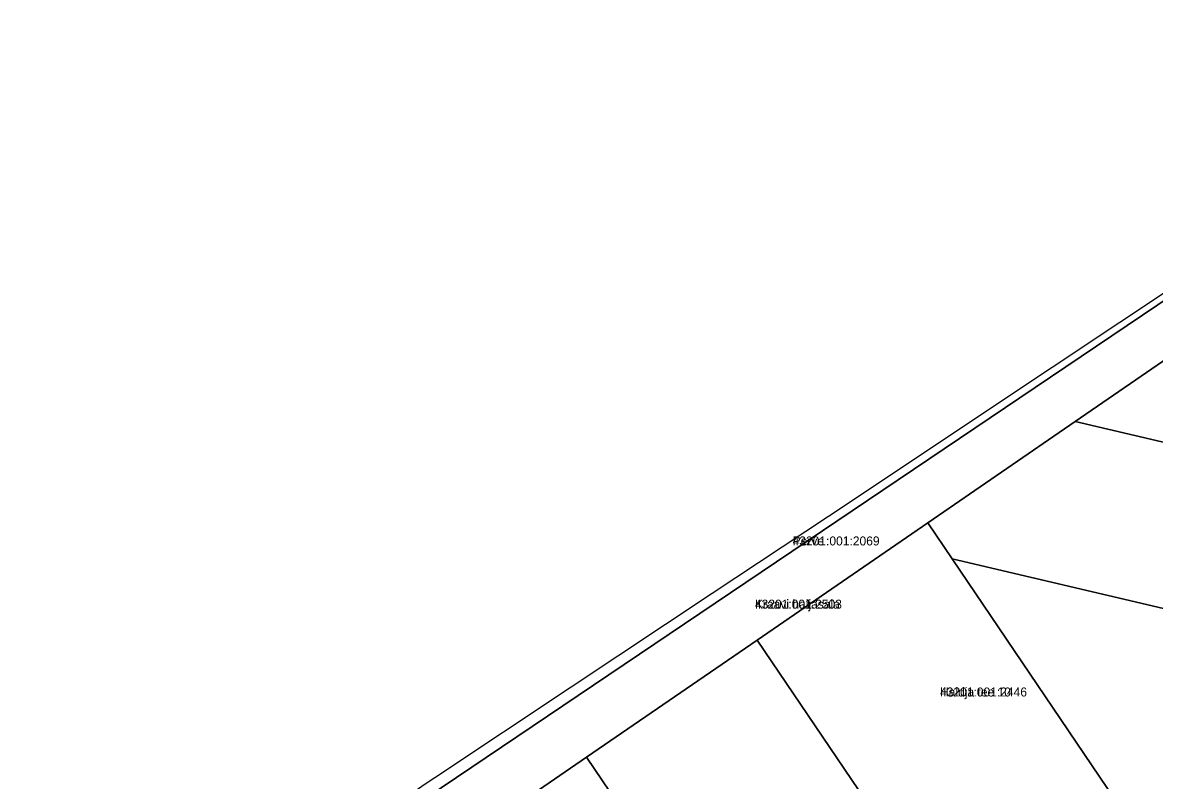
# Model space of a CAD drawing. Extents: x 661852 to 683758, y 6469495 to 6482657.
# Drawn here: x 663149.3 to 663337.9, y 6470350.3 to 6470476.5 of the extents above; entities that cross this region are included whole.
import ezdxf

# ---------------------------------------------------------------- set-up
doc = ezdxf.new("R2010")
doc.units = 0
for name, color, linetype in [('L_AADRESS', 7, 'Continuous'), ('PIIR', 7, 'Continuous'), ('TUNNUS', 7, 'Continuous')]:
    doc.layers.add(name, color=color, linetype=linetype)

msp = doc.modelspace()

# ---------------------------------------------------------------- linework, layer by layer
at = {"layer": 'PIIR'}
for points in [[(663386.73, 6470461.98), (663152.91, 6470304.5), (663149.63, 6470302.29), (663149.29, 6470302.91), (663152.5, 6470305.15), (663176.5, 6470321.88), (663197.37, 6470336.43), (663216.36, 6470349.67), (663217.96, 6470350.73), (663240.69, 6470365.84), (663264.21, 6470381.45), (663287.53, 6470396.88), (663309.62, 6470411.62), (663332.17, 6470426.61), (663387.19, 6470463.21), (663407.23, 6470476.53), (663407.44, 6470475.89), (663388.39, 6470463.06)], [(663158.41, 6470295.77), (663152.91, 6470304.5), (663386.73, 6470461.98), (663384.15, 6470450.91), (663324.73, 6470410.08), (663300.15, 6470393.19), (663271.71, 6470373.65), (663243.28, 6470354.11), (663214.84, 6470334.57), (663186.41, 6470315.03)], [(663376.34, 6470397.96), (663324.73, 6470410.08), (663384.15, 6470450.91), (663382.48, 6470443.81), (663386.86, 6470442.78)], [(663304.22, 6470387.16), (663300.15, 6470393.19), (663324.73, 6470410.08), (663376.34, 6470397.96), (663370.17, 6470371.68)], [(663297.09, 6470336.11), (663271.71, 6470373.65), (663300.15, 6470393.19), (663304.22, 6470387.16), (663332.64, 6470345.13), (663327.57, 6470345.04), (663316.44, 6470343.1), (663306.8, 6470340.26)], [(663332.64, 6470345.13), (663304.22, 6470387.16), (663370.17, 6470371.68), (663364.16, 6470346.08), (663359.35, 6470343.1), (663344.92, 6470345.34)], [(663267.97, 6470317.59), (663243.28, 6470354.11), (663271.71, 6470373.65), (663297.09, 6470336.11), (663285.82, 6470329.67)], [(663239.39, 6470298.27), (663214.84, 6470334.57), (663243.28, 6470354.11), (663267.97, 6470317.59)]]:
    msp.add_lwpolyline(points, close=True, dxfattribs=at)

# ---------------------------------------------------------------- texts
at = {"layer": 'L_AADRESS'}
for s, p in [('Perve', (663277.61, 6470389.41)), ('Kraavi haljasala', (663271.33, 6470378.88)), ('Haldja tee 10', (663302.18, 6470364.24))]:
    msp.add_text(s, height=1.5, dxfattribs=at).set_placement(p)
at = {"layer": 'TUNNUS'}
for s, p in [('43201:001:2069', (663277.61, 6470389.41)), ('43201:001:2503', (663271.33, 6470378.88)), ('43201:001:2446', (663302.18, 6470364.24))]:
    msp.add_text(s, height=1.5, dxfattribs=at).set_placement(p)

doc.saveas('drawing.dxf')
